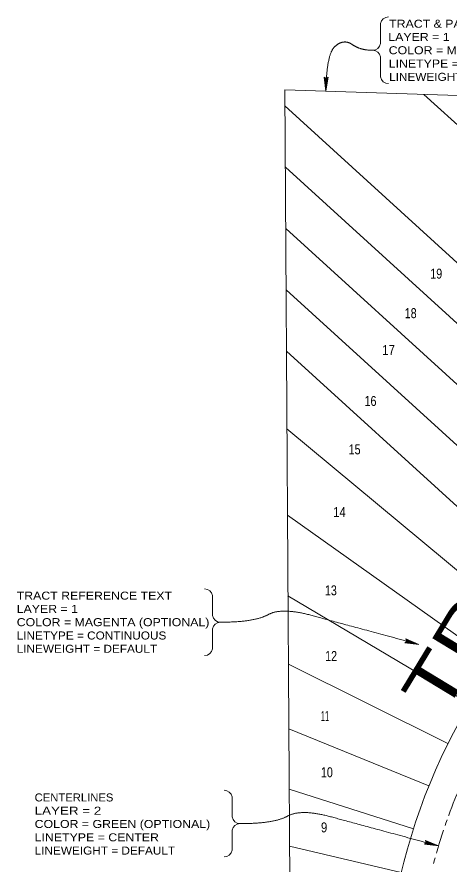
# Model space of a CAD drawing. Extents: x 6387474 to 6390971, y 1972046 to 1973920.
# Drawn here: x 6388805 to 6389237, y 1972779 to 1973626 of the extents above; entities that cross this region are included whole.
import ezdxf

# ---------------------------------------------------------------- set-up
doc = ezdxf.new("R2010")
doc.units = 0
doc.header["$LTSCALE"] = 4
doc.linetypes.add('LONG_DASH_SHORT_DASH', pattern=[9.9, 6, -1.2, 1.5, -1.2])
for name, color, linetype, lineweight in [('1', 7, 'Continuous', 13), ('2', 7, 'LONG_DASH_SHORT_DASH', 13), ('3', 7, 'Continuous', 13), ('4', 7, 'Continuous', 13), ('8', 7, 'Continuous', 13)]:
    doc.layers.add(name, color=color, linetype=linetype, lineweight=lineweight)
doc.layers.add('7', color=7, linetype='Continuous')

msp = doc.modelspace()

# ---------------------------------------------------------------- hatches: boundary and pattern name
at = {"layer": '8'}
for points in [[(6389113.607, 1973551.444), (6389112.203, 1973565.047), (6389111.811, 1973565.472)], [(6389113.607, 1973551.444), (6389112.682, 1973564.723), (6389112.203, 1973565.047)], [(6389113.607, 1973551.444), (6389113.223, 1973564.518), (6389112.682, 1973564.723)], [(6389113.796, 1973564.443), (6389113.223, 1973564.518), (6389113.607, 1973551.444)], [(6389115.811, 1973565.414), (6389115.407, 1973565), (6389113.607, 1973551.444)], [(6389115.407, 1973565), (6389114.918, 1973564.691), (6389113.607, 1973551.444)], [(6389114.918, 1973564.691), (6389114.372, 1973564.501), (6389113.607, 1973551.444)], [(6389114.372, 1973564.501), (6389113.796, 1973564.443), (6389113.607, 1973551.444)], [(6389193.519, 1973004.322), (6389193.819, 1973003.829), (6389206.51, 1972998.735)], [(6389193.819, 1973003.829), (6389193.999, 1973003.279), (6389206.51, 1972998.735)], [(6389206.51, 1972998.735), (6389192.983, 1973000.736), (6389192.474, 1973000.461)], [(6389206.51, 1972998.735), (6389193.415, 1973001.12), (6389192.983, 1973000.736)], [(6389206.51, 1972998.735), (6389193.747, 1973001.594), (6389193.415, 1973001.12)], [(6389193.962, 1973002.131), (6389193.747, 1973001.594), (6389206.51, 1972998.735)], [(6389194.047, 1973002.703), (6389193.962, 1973002.131), (6389206.51, 1972998.735)], [(6389193.999, 1973003.279), (6389194.047, 1973002.703), (6389206.51, 1972998.735)], [(6389225.987, 1972797.469), (6389213.224, 1972800.327), (6389212.892, 1972799.854)], [(6389212.996, 1972803.056), (6389213.296, 1972802.562), (6389225.987, 1972797.469)], [(6389213.439, 1972800.864), (6389213.224, 1972800.327), (6389225.987, 1972797.469)], [(6389213.296, 1972802.562), (6389213.476, 1972802.013), (6389225.987, 1972797.469)], [(6389213.524, 1972801.436), (6389213.439, 1972800.864), (6389225.987, 1972797.469)], [(6389213.476, 1972802.013), (6389213.524, 1972801.436), (6389225.987, 1972797.469)], [(6389225.987, 1972797.469), (6389212.46, 1972799.47), (6389211.951, 1972799.195)], [(6389225.987, 1972797.469), (6389212.892, 1972799.854), (6389212.46, 1972799.47)]]:
    msp.add_hatch(color=256, dxfattribs=at).paths.add_polyline_path(points)

# ---------------------------------------------------------------- linework, layer by layer
at = {"layer": '1'}
for p, q in [((6389526.666, 1973538.455), (6389072.576, 1973552.734)), ((6389072.576, 1973552.734), (6389079.624, 1972387.996))]:
    msp.add_line(p, q, dxfattribs=at)
at = {"layer": '2'}
msp.add_arc((6389771.658, 1972632.718), 570, 137.65572, 165.09236, dxfattribs=at)
at = {"layer": '3'}
for p, q in [((6389463.195, 1973318.918), (6389211.423, 1973548.368)), ((6389461.63, 1973182.312), (6389072.673, 1973536.784)), ((6389431.586, 1973148.835), (6389073.043, 1973475.589)), ((6389401.274, 1973115.575), (6389073.413, 1973414.367)), ((6389370.963, 1973082.315), (6389073.784, 1973353.146)), ((6389340.651, 1973049.055), (6389074.154, 1973291.925)), ((6389311.975, 1973016.765), (6389074.625, 1973214.186)), ((6389283.443, 1972979.771), (6389075.147, 1973127.843)), ((6389257.09, 1972939.344), (6389075.633, 1973047.475)), ((6389235.428, 1972899.651), (6389076.048, 1972978.993)), ((6389216.483, 1972857.614), (6389076.439, 1972914.346)), ((6389200.964, 1972814.663), (6389076.802, 1972854.248)), ((6389188.792, 1972770.788), (6389077.147, 1972797.257))]:
    msp.add_line(p, q, dxfattribs=at)
at = {"layer": '4'}
msp.add_arc((6389771.661, 1972632.72), 599, 137.65605, 180.34667, dxfattribs=at)
at = {"layer": '8'}
for p, q in [((6389168.158, 1973619.048), (6389168.158, 1973599.068)), ((6389168.158, 1973565.762), (6389168.158, 1973585.742)), ((6389000.343, 1973047.64), (6389000.343, 1973027.66)), ((6389000.343, 1972994.352), (6389000.343, 1973014.332)), ((6389019.82, 1972846.374), (6389019.82, 1972826.394)), ((6389019.82, 1972793.086), (6389019.82, 1972813.066))]:
    msp.add_line(p, q, dxfattribs=at)
for points in [[(6389124.97, 1973598.134), (6389124.64, 1973597.914), (6389124.31, 1973597.684), (6389123.979, 1973597.444), (6389123.647, 1973597.194), (6389123.315, 1973596.934), (6389122.982, 1973596.664), (6389122.652, 1973596.384), (6389122.328, 1973596.074), (6389122.01, 1973595.744), (6389121.698, 1973595.394), (6389121.391, 1973595.024), (6389121.091, 1973594.634), (6389120.796, 1973594.224), (6389120.507, 1973593.784), (6389120.224, 1973593.324), (6389119.947, 1973592.844), (6389119.676, 1973592.344), (6389119.411, 1973591.814), (6389119.151, 1973591.264), (6389118.898, 1973590.704), (6389118.65, 1973590.114), (6389118.409, 1973589.494), (6389118.173, 1973588.864), (6389117.943, 1973588.204), (6389117.719, 1973587.534), (6389117.501, 1973586.834), (6389117.289, 1973586.104), (6389117.082, 1973585.364), (6389116.882, 1973584.594), (6389116.687, 1973583.814), (6389116.499, 1973583.004), (6389116.316, 1973582.174), (6389116.139, 1973581.314), (6389115.968, 1973580.444), (6389115.803, 1973579.544), (6389115.644, 1973578.624), (6389115.49, 1973577.684), (6389115.343, 1973576.724), (6389115.201, 1973575.734), (6389115.066, 1973574.734), (6389114.936, 1973573.704), (6389114.812, 1973572.654), (6389114.694, 1973571.584), (6389114.582, 1973570.484), (6389114.476, 1973569.374), (6389114.375, 1973568.234), (6389114.281, 1973567.074), (6389114.192, 1973565.894), (6389114.11, 1973564.684), (6389114.033, 1973563.464), (6389113.962, 1973562.214), (6389113.897, 1973560.944), (6389113.838, 1973559.654), (6389113.785, 1973558.344), (6389113.737, 1973557.004), (6389113.696, 1973555.644), (6389113.66, 1973554.264), (6389113.631, 1973552.864), (6389113.607, 1973551.444)], [(6389141.064, 1973597.314), (6389140.75, 1973597.514), (6389140.44, 1973597.724), (6389140.132, 1973597.934), (6389139.828, 1973598.144), (6389139.525, 1973598.364), (6389139.221, 1973598.564), (6389138.917, 1973598.754), (6389138.613, 1973598.944), (6389138.307, 1973599.114), (6389138.001, 1973599.284), (6389137.695, 1973599.434), (6389137.388, 1973599.584), (6389137.081, 1973599.724), (6389136.772, 1973599.854), (6389136.464, 1973599.974), (6389136.154, 1973600.084), (6389135.845, 1973600.184), (6389135.534, 1973600.274), (6389135.223, 1973600.364), (6389134.912, 1973600.434), (6389134.599, 1973600.494), (6389134.287, 1973600.554), (6389133.973, 1973600.594), (6389133.66, 1973600.634), (6389133.345, 1973600.664), (6389133.03, 1973600.684), (6389132.715, 1973600.694), (6389132.399, 1973600.694), (6389132.082, 1973600.684), (6389131.765, 1973600.664), (6389131.447, 1973600.634), (6389131.128, 1973600.594), (6389130.809, 1973600.554), (6389130.49, 1973600.494), (6389130.17, 1973600.424), (6389129.849, 1973600.354), (6389129.528, 1973600.274), (6389129.206, 1973600.174), (6389128.883, 1973600.074), (6389128.56, 1973599.964), (6389128.237, 1973599.844), (6389127.913, 1973599.714), (6389127.588, 1973599.574), (6389127.263, 1973599.424), (6389126.937, 1973599.274), (6389126.611, 1973599.104), (6389126.284, 1973598.934), (6389125.956, 1973598.744), (6389125.628, 1973598.554), (6389125.299, 1973598.344), (6389124.97, 1973598.134)], [(6389160.273, 1973592.404), (6389159.806, 1973592.404), (6389159.342, 1973592.414), (6389158.881, 1973592.424), (6389158.423, 1973592.434), (6389157.968, 1973592.454), (6389157.517, 1973592.474), (6389157.068, 1973592.504), (6389156.623, 1973592.534), (6389156.181, 1973592.574), (6389155.742, 1973592.614), (6389155.306, 1973592.654), (6389154.873, 1973592.704), (6389154.443, 1973592.754), (6389154.017, 1973592.804), (6389153.594, 1973592.864), (6389153.173, 1973592.924), (6389152.756, 1973592.994), (6389152.342, 1973593.064), (6389151.931, 1973593.144), (6389151.524, 1973593.224), (6389151.119, 1973593.304), (6389150.718, 1973593.394), (6389150.319, 1973593.484), (6389149.924, 1973593.584), (6389149.532, 1973593.684), (6389149.143, 1973593.784), (6389148.758, 1973593.894), (6389148.375, 1973594.004), (6389147.996, 1973594.124), (6389147.619, 1973594.244), (6389147.246, 1973594.374), (6389146.876, 1973594.494), (6389146.509, 1973594.634), (6389146.145, 1973594.764), (6389145.784, 1973594.914), (6389145.427, 1973595.054), (6389145.072, 1973595.204), (6389144.721, 1973595.354), (6389144.373, 1973595.514), (6389144.028, 1973595.674), (6389143.686, 1973595.844), (6389143.347, 1973596.014), (6389143.012, 1973596.184), (6389142.679, 1973596.364), (6389142.35, 1973596.544), (6389142.024, 1973596.734), (6389141.701, 1973596.924), (6389141.381, 1973597.114), (6389141.064, 1973597.314)], [(6389111.811, 1973565.472), (6389113.607, 1973551.444), (6389115.81, 1973565.414)], [(6389053.474, 1973027.384), (6389054.034, 1973027.644), (6389054.58, 1973027.914), (6389055.111, 1973028.184), (6389055.627, 1973028.464), (6389056.142, 1973028.744), (6389056.669, 1973029.004), (6389057.207, 1973029.264), (6389057.756, 1973029.504), (6389058.316, 1973029.734), (6389058.888, 1973029.954), (6389059.471, 1973030.164), (6389060.066, 1973030.364), (6389060.672, 1973030.554), (6389061.289, 1973030.734), (6389061.918, 1973030.904), (6389062.558, 1973031.054), (6389063.209, 1973031.204), (6389063.872, 1973031.334), (6389064.546, 1973031.454), (6389065.231, 1973031.564), (6389065.928, 1973031.664), (6389066.636, 1973031.754), (6389067.356, 1973031.834), (6389068.087, 1973031.904), (6389068.829, 1973031.954), (6389069.582, 1973032.004), (6389070.347, 1973032.034), (6389071.124, 1973032.064), (6389071.911, 1973032.074), (6389072.71, 1973032.074), (6389073.521, 1973032.064), (6389074.342, 1973032.044), (6389075.175, 1973032.014), (6389076.02, 1973031.974), (6389076.876, 1973031.914), (6389077.743, 1973031.854), (6389078.621, 1973031.774), (6389079.511, 1973031.684), (6389080.412, 1973031.594), (6389081.325, 1973031.484), (6389082.249, 1973031.364), (6389083.184, 1973031.234), (6389084.131, 1973031.094), (6389085.089, 1973030.934), (6389086.058, 1973030.774), (6389087.039, 1973030.594), (6389088.031, 1973030.414), (6389089.035, 1973030.214), (6389090.049, 1973030.004), (6389091.076, 1973029.794), (6389092.113, 1973029.564)], [(6389092.113, 1973029.564), (6389093.162, 1973029.324), (6389094.222, 1973029.064), (6389095.294, 1973028.804), (6389096.377, 1973028.534), (6389097.471, 1973028.244), (6389098.577, 1973027.954), (6389099.706, 1973027.644), (6389100.869, 1973027.334), (6389102.068, 1973027.004), (6389103.302, 1973026.674), (6389104.57, 1973026.324), (6389105.873, 1973025.974), (6389107.212, 1973025.614), (6389108.585, 1973025.234), (6389109.993, 1973024.854), (6389111.436, 1973024.464), (6389112.914, 1973024.064), (6389114.427, 1973023.654), (6389115.974, 1973023.234), (6389117.557, 1973022.804), (6389119.175, 1973022.374), (6389120.827, 1973021.924), (6389122.514, 1973021.464), (6389124.237, 1973021.004), (6389125.994, 1973020.524), (6389127.786, 1973020.044), (6389129.613, 1973019.544), (6389131.475, 1973019.044), (6389133.372, 1973018.524), (6389135.304, 1973018.004), (6389137.27, 1973017.474), (6389139.272, 1973016.934), (6389141.308, 1973016.374), (6389143.38, 1973015.814), (6389145.486, 1973015.244), (6389147.627, 1973014.664), (6389149.803, 1973014.084), (6389152.014, 1973013.484), (6389154.26, 1973012.874), (6389156.541, 1973012.254), (6389158.857, 1973011.624), (6389161.207, 1973010.994), (6389163.593, 1973010.344), (6389166.014, 1973009.694), (6389168.469, 1973009.024), (6389170.959, 1973008.354), (6389173.484, 1973007.674), (6389176.045, 1973006.974), (6389178.64, 1973006.274), (6389181.27, 1973005.564), (6389183.934, 1973004.844), (6389186.634, 1973004.114), (6389189.369, 1973003.374), (6389192.138, 1973002.624), (6389194.943, 1973001.864), (6389197.782, 1973001.094), (6389200.657, 1973000.314), (6389203.566, 1972999.534), (6389206.51, 1972998.734)], [(6389008.231, 1973020.994), (6389009.503, 1973020.994), (6389010.761, 1973021.004), (6389012.003, 1973021.024), (6389013.232, 1973021.034), (6389014.446, 1973021.064), (6389015.645, 1973021.094), (6389016.83, 1973021.124), (6389018, 1973021.164), (6389019.156, 1973021.214), (6389020.297, 1973021.264), (6389021.423, 1973021.314), (6389022.535, 1973021.374), (6389023.633, 1973021.444), (6389024.716, 1973021.514), (6389025.785, 1973021.594), (6389026.839, 1973021.674), (6389027.878, 1973021.764), (6389028.903, 1973021.854), (6389029.914, 1973021.954), (6389030.91, 1973022.064), (6389031.891, 1973022.164), (6389032.858, 1973022.284), (6389033.81, 1973022.404), (6389034.748, 1973022.524), (6389035.671, 1973022.654), (6389036.58, 1973022.794), (6389037.475, 1973022.934), (6389038.354, 1973023.084), (6389039.219, 1973023.234), (6389040.07, 1973023.384), (6389040.906, 1973023.554), (6389041.728, 1973023.714), (6389042.535, 1973023.894), (6389043.328, 1973024.074), (6389044.106, 1973024.254), (6389044.869, 1973024.444), (6389045.618, 1973024.634), (6389046.353, 1973024.834), (6389047.073, 1973025.044), (6389047.778, 1973025.254), (6389048.469, 1973025.464), (6389049.146, 1973025.684), (6389049.807, 1973025.914), (6389050.455, 1973026.144), (6389051.088, 1973026.384), (6389051.706, 1973026.624), (6389052.31, 1973026.874), (6389052.899, 1973027.124), (6389053.474, 1973027.384)], [(6389192.474, 1973000.461), (6389206.51, 1972998.735), (6389193.519, 1973004.322)], [(6389027.708, 1972819.734), (6389028.98, 1972819.734), (6389030.238, 1972819.744), (6389031.48, 1972819.754), (6389032.709, 1972819.774), (6389033.923, 1972819.794), (6389035.122, 1972819.824), (6389036.307, 1972819.864), (6389037.477, 1972819.904), (6389038.633, 1972819.944), (6389039.774, 1972819.994), (6389040.9, 1972820.054), (6389042.012, 1972820.114), (6389043.11, 1972820.184), (6389044.193, 1972820.254), (6389045.262, 1972820.324), (6389046.316, 1972820.414), (6389047.355, 1972820.494), (6389048.38, 1972820.594), (6389049.391, 1972820.694), (6389050.387, 1972820.794), (6389051.368, 1972820.904), (6389052.335, 1972821.014), (6389053.287, 1972821.134), (6389054.225, 1972821.264), (6389055.148, 1972821.394), (6389056.057, 1972821.524), (6389056.952, 1972821.664), (6389057.831, 1972821.814), (6389058.696, 1972821.964), (6389059.547, 1972822.124), (6389060.383, 1972822.284), (6389061.205, 1972822.454), (6389062.012, 1972822.624), (6389062.805, 1972822.804), (6389063.583, 1972822.984), (6389064.346, 1972823.174), (6389065.095, 1972823.374), (6389065.83, 1972823.574), (6389066.55, 1972823.774), (6389067.255, 1972823.984), (6389067.946, 1972824.204), (6389068.623, 1972824.424), (6389069.284, 1972824.644), (6389069.932, 1972824.874), (6389070.565, 1972825.114), (6389071.183, 1972825.354), (6389071.787, 1972825.604), (6389072.376, 1972825.854), (6389072.951, 1972826.114)], [(6389072.951, 1972826.114), (6389073.511, 1972826.374), (6389074.057, 1972826.644), (6389074.588, 1972826.924), (6389075.104, 1972827.194), (6389075.619, 1972827.474), (6389076.146, 1972827.744), (6389076.684, 1972827.994), (6389077.233, 1972828.234), (6389077.793, 1972828.474), (6389078.365, 1972828.694), (6389078.948, 1972828.904), (6389079.543, 1972829.104), (6389080.149, 1972829.294), (6389080.766, 1972829.464), (6389081.395, 1972829.634), (6389082.035, 1972829.784), (6389082.686, 1972829.934), (6389083.349, 1972830.064), (6389084.023, 1972830.184), (6389084.708, 1972830.304), (6389085.405, 1972830.404), (6389086.113, 1972830.494), (6389086.833, 1972830.564), (6389087.564, 1972830.634), (6389088.306, 1972830.694), (6389089.059, 1972830.734), (6389089.824, 1972830.774), (6389090.601, 1972830.794), (6389091.388, 1972830.804), (6389092.187, 1972830.804), (6389092.998, 1972830.794), (6389093.819, 1972830.774), (6389094.652, 1972830.744), (6389095.497, 1972830.704), (6389096.353, 1972830.654), (6389097.22, 1972830.584), (6389098.098, 1972830.514), (6389098.988, 1972830.424), (6389099.889, 1972830.324), (6389100.802, 1972830.214), (6389101.726, 1972830.094), (6389102.661, 1972829.964), (6389103.608, 1972829.824), (6389104.566, 1972829.674), (6389105.535, 1972829.504), (6389106.516, 1972829.334), (6389107.508, 1972829.144), (6389108.512, 1972828.954), (6389109.526, 1972828.744), (6389110.553, 1972828.524), (6389111.59, 1972828.294)], [(6389111.59, 1972828.294), (6389112.639, 1972828.054), (6389113.699, 1972827.804), (6389114.771, 1972827.534), (6389115.854, 1972827.264), (6389116.948, 1972826.984), (6389118.054, 1972826.684), (6389119.183, 1972826.374), (6389120.346, 1972826.064), (6389121.545, 1972825.734), (6389122.779, 1972825.404), (6389124.047, 1972825.064), (6389125.35, 1972824.704), (6389126.689, 1972824.344), (6389128.062, 1972823.974), (6389129.47, 1972823.594), (6389130.913, 1972823.204), (6389132.391, 1972822.804), (6389133.904, 1972822.394), (6389135.451, 1972821.974), (6389137.034, 1972821.544), (6389138.652, 1972821.104), (6389140.304, 1972820.654), (6389141.991, 1972820.204), (6389143.714, 1972819.734), (6389145.471, 1972819.254), (6389147.263, 1972818.774), (6389149.09, 1972818.274), (6389150.952, 1972817.774), (6389152.849, 1972817.264), (6389154.781, 1972816.734), (6389156.747, 1972816.204), (6389158.749, 1972815.664), (6389160.785, 1972815.114), (6389162.857, 1972814.554), (6389164.963, 1972813.984), (6389167.104, 1972813.404), (6389169.28, 1972812.814), (6389171.491, 1972812.214), (6389173.737, 1972811.604), (6389176.018, 1972810.994), (6389178.334, 1972810.364), (6389180.684, 1972809.724), (6389183.07, 1972809.084), (6389185.491, 1972808.424), (6389187.946, 1972807.764), (6389190.436, 1972807.084), (6389192.961, 1972806.404), (6389195.522, 1972805.714), (6389198.117, 1972805.014), (6389200.747, 1972804.294), (6389203.411, 1972803.574), (6389206.111, 1972802.844), (6389208.846, 1972802.104), (6389211.615, 1972801.354), (6389214.42, 1972800.594), (6389217.259, 1972799.834), (6389220.134, 1972799.054), (6389223.043, 1972798.264), (6389225.987, 1972797.464)], [(6389211.951, 1972799.195), (6389225.987, 1972797.469), (6389212.996, 1972803.056)]]:
    msp.add_lwpolyline(points, dxfattribs=at)
for points in [[(6389113.607, 1973551.444), (6389112.203, 1973565.047), (6389111.811, 1973565.472)], [(6389113.607, 1973551.444), (6389112.682, 1973564.723), (6389112.203, 1973565.047)], [(6389113.607, 1973551.444), (6389113.223, 1973564.518), (6389112.682, 1973564.723)], [(6389113.796, 1973564.443), (6389113.223, 1973564.518), (6389113.607, 1973551.444)], [(6389115.811, 1973565.414), (6389115.407, 1973565), (6389113.607, 1973551.444)], [(6389115.407, 1973565), (6389114.918, 1973564.691), (6389113.607, 1973551.444)], [(6389114.918, 1973564.691), (6389114.372, 1973564.501), (6389113.607, 1973551.444)], [(6389114.372, 1973564.501), (6389113.796, 1973564.443), (6389113.607, 1973551.444)], [(6389193.519, 1973004.322), (6389193.819, 1973003.829), (6389206.51, 1972998.735)], [(6389193.819, 1973003.829), (6389193.999, 1973003.279), (6389206.51, 1972998.735)], [(6389206.51, 1972998.735), (6389192.983, 1973000.736), (6389192.474, 1973000.461)], [(6389206.51, 1972998.735), (6389193.415, 1973001.12), (6389192.983, 1973000.736)], [(6389206.51, 1972998.735), (6389193.747, 1973001.594), (6389193.415, 1973001.12)], [(6389193.962, 1973002.131), (6389193.747, 1973001.594), (6389206.51, 1972998.735)], [(6389194.047, 1973002.703), (6389193.962, 1973002.131), (6389206.51, 1972998.735)], [(6389193.999, 1973003.279), (6389194.047, 1973002.703), (6389206.51, 1972998.735)], [(6389225.987, 1972797.469), (6389213.224, 1972800.327), (6389212.892, 1972799.854)], [(6389212.996, 1972803.056), (6389213.296, 1972802.562), (6389225.987, 1972797.469)], [(6389213.439, 1972800.864), (6389213.224, 1972800.327), (6389225.987, 1972797.469)], [(6389213.296, 1972802.562), (6389213.476, 1972802.013), (6389225.987, 1972797.469)], [(6389213.524, 1972801.436), (6389213.439, 1972800.864), (6389225.987, 1972797.469)], [(6389213.476, 1972802.013), (6389213.524, 1972801.436), (6389225.987, 1972797.469)], [(6389225.987, 1972797.469), (6389212.46, 1972799.47), (6389211.951, 1972799.195)], [(6389225.987, 1972797.469), (6389212.892, 1972799.854), (6389212.46, 1972799.47)]]:
    msp.add_lwpolyline(points, close=True, dxfattribs=at)
for centre, radius, start, end in [((6389176.048, 1973617.711), 8, 90, 170.38048), ((6389160.272, 1973600.405), 8, 270, 350.38048), ((6389160.272, 1973584.405), 8, 9.61952, 90), ((6389113.833, 1973566.943), 2.5, 216.03839, 322.2986), ((6389176.047, 1973567.099), 8, 189.61952, 270), ((6388992.456, 1973046.303), 8, 9.61952, 90), ((6389008.231, 1973028.997), 8, 189.61952, 270), ((6389008.231, 1973012.997), 8, 90, 170.38048), ((6389191.548, 1973002.783), 2.5, 291.73131, 37.99152), ((6388992.456, 1972995.69), 8, 270, 350.38048), ((6389011.933, 1972845.037), 8, 9.61952, 90), ((6389027.708, 1972827.73), 8, 189.61952, 270), ((6389027.708, 1972811.73), 8, 90, 170.38048), ((6389211.025, 1972801.517), 2.5, 291.73131, 37.99152), ((6389011.933, 1972794.424), 8, 270, 350.38048)]:
    msp.add_arc(centre, radius, start, end, dxfattribs=at)

# ---------------------------------------------------------------- texts
at = {"layer": '1', "width": 1.35}
msp.add_text('TR 4321X', height=50, rotation=58.729, dxfattribs=at).set_placement((6389230.058, 1972925.588))
at = {"layer": '7'}
for s, width, p in [('19', 0.8, (6389217.787, 1973364.22)), ('18', 0.8, (6389192.27, 1973324.752)), ('17', 0.85, (6389169.853, 1973288.016)), ('16', 0.8, (6389152.147, 1973236.982)), ('15', 0.8, (6389136.294, 1973188.641)), ('14', 0.85, (6389120.72, 1973126.005)), ('13', 0.8, (6389112.574, 1973047.822)), ('12', 0.8, (6389112.81, 1972982.197)), ('11', 0.55, (6389108.581, 1972922.283)), ('10', 0.8, (6389108.581, 1972866.053)), ('9', 0.85, (6389108.581, 1972810.995))]:
    msp.add_text(s, height=10, dxfattribs=dict(at, width=width)).set_placement(p)
at = {"layer": '8'}
for s, width, p in [('TRACT & PARCEL BOUNDARY', 1.15, (6389176.692, 1973614.945)), ('LAYER = 1', 1.15, (6389175.88, 1973601.697)), ('COLOR = MAGENTA (OPTIONAL)', 1.15, (6389176.272, 1973588.439)), ('LINETYPE = POLYLINE (OPTIONAL)', 1.15, (6389176.272, 1973575.119)), ('LINEWEIGHT = DEFAULT', 1.1, (6389176.664, 1973561.861)), ('TRACT REFERENCE TEXT', 1.15, (6388804.754, 1973043.537)), ('LAYER = 1', 1.15, (6388804.776, 1973030.287)), ('COLOR = MAGENTA (OPTIONAL)', 1.15, (6388804.79, 1973017.031)), ('LINETYPE = CONTINUOUS', 1.1, (6388804.79, 1973003.711)), ('LINEWEIGHT = DEFAULT', 1.1, (6388804.782, 1972990.453)), ('CENTERLINES', 1.05, (6388822.683, 1972841.914)), ('LAYER = 2', 1.25, (6388822.705, 1972828.664)), ('COLOR = GREEN (OPTIONAL)', 1.15, (6388822.719, 1972815.408)), ('LINETYPE = CENTER', 1.15, (6388822.719, 1972802.088)), ('LINEWEIGHT = DEFAULT', 1.1, (6388822.711, 1972788.83))]:
    msp.add_text(s, height=8, dxfattribs=dict(at, width=width)).set_placement(p)

doc.saveas('drawing.dxf')
